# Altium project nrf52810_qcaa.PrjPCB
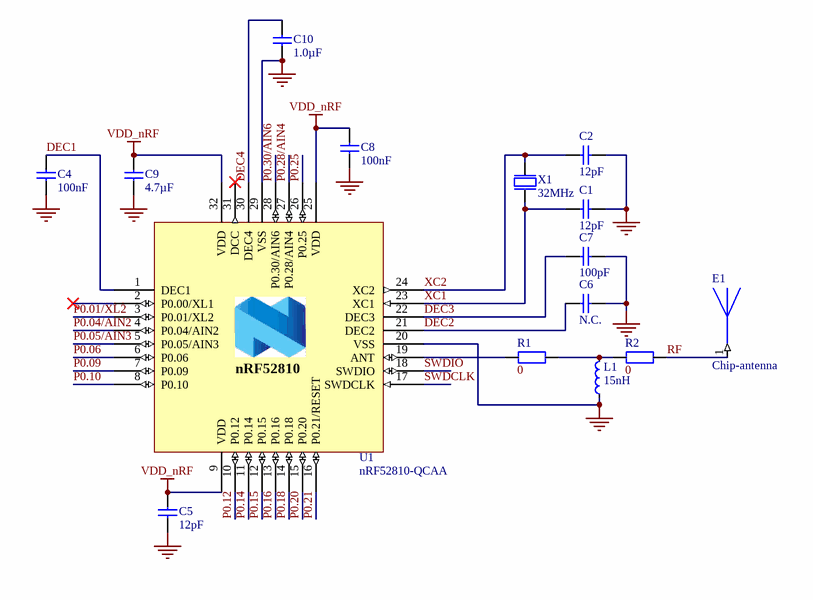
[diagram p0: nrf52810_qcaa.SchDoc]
1 sheet, 15 parts. Net scope: global (net labels, ports and power ports of the same name join across sheets).
Board file: nrf52810_qcaa.PcbDoc

## Sheet nrf52810_qcaa.SchDoc: nRF52810-QCAA Reference Layout
size A4; Revision: 1.0; SheetNumber: 1; SheetTotal: 1; DrawnBy: RUBR; DocumentSize: A4; PCAName: nRF52810-QCAA Reference Layout

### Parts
C1  12pF  [CAPC1005X04L]
C2  12pF  [CAPC1005X04L]
C4  100nF  [CAPC1005X04L]
C5  12pF  [CAPC1005X04L]
C6  N.C.  [CAPC1005X04L]
C7  100pF  [CAPC1005X04L]
C8  100nF  [CAPC1005X04L]
C9  4.7µF  [CAPC1608X06L]
C10  1.0µF  [CAPC1608X06L]
E1  Chip-antenna  [C03-chip-antenna]
L1  15nH  [INDC1005X04L]
R1  0  [R-0402-1005X40]
R2  0  [R-0402-1005X40]
U1  nRF52810-QCAA  [Nordic_QFN50P500X500X90-33N]
X1  32MHz  [BT-XTAL_2016]

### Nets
GND: C1.2 C2.2 C4.2 C5.2 C6.1 C7.2 C8.2 C9.2 C10.1 L1.1 U1.20(VSS) U1.29(VSS) U1.33 X1.2(GND) X1.4(GND)
VDD_nRF: C5.1 C8.1 C9.1 U1.9(VDD) U1.25(VDD) U1.32(VDD)
DEC1: C4.1 U1.1(DEC1)
DEC2: C6.2 U1.21(DEC2)
DEC3: C7.1 U1.22(DEC3)
DEC4: C10.2 U1.30(DEC4)
P0.01/XL2: U1.3(P0.01/XL2)
P0.04/AIN2: U1.4(P0.04/AIN2)
P0.05/AIN3: U1.5(P0.05/AIN3)
P0.06: U1.6(P0.06)
P0.09: U1.7(P0.09)
P0.10: U1.8(P0.10)
P0.12: U1.10(P0.12)
P0.14: U1.11(P0.14)
P0.15: U1.12(P0.15)
P0.16: U1.13(P0.16)
P0.18: U1.14(P0.18)
P0.20: U1.15(P0.20)
P0.21: U1.16(P0.21/RESET)
P0.25: U1.26(P0.25)
P0.28/AIN4: U1.27(P0.28/AIN4)
P0.30/AIN6: U1.28(P0.30/AIN6)
RF: E1.1(FEED) R2.2
SWDCLK: U1.17(SWDCLK)
SWDIO: U1.18(SWDIO)
XC1: C1.1 U1.23(XC1) X1.1(inp)
XC2: C2.1 U1.24(XC2) X1.3(out)
NetL1_2: L1.2 R1.2 R2.1
NetR1_1: R1.1 U1.19(ANT)

Not connected (* = marked no-connect by the designer): U1 2(P0.00/XL1)* 31(DCC)*

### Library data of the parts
C1 C2 = C0402-12p: Capacitor, NP0, ±2%; Note: 50V
C4 C8 = C0402-100n: Capacitor, X7R, ±10%; Note: 16V
C5 = CAP_0402: Capacitor, NP0, ±2%; Part Number: C0402-12p; Note: 50V
C6 = C0402-N.C.: Not mounted; Assembly: Not mounted
C7 = C0402-100p: Capacitor, NP0, ±5%; Note: 50V
C9 = C0603-4µ7: Capacitor, X5R, ±10%; Note: 6.3V
C10 = C0603-1µ0: Capacitor, X7R, ±10%; Note: 16V
E1 = Chip-antenna: antenna; MF: Linx; MP: ANT-868-CHP-T
L1 = IND_0402: High frequency chip inductor ±10%; Part Number: L0402-15n
R1 R2 = R-0402: 0402
U1 = nRF52810-QCAA: Multi-protocol Bluetooth Low Energy, ANT and 2.4GHz proprietary system-on-chip; Manufacturer: Nordic Semiconductor; Note: nRF52810 - QFN32 5x5 0.5mm pitch
X1 = XTAL_SMD2016_32MHz_8pF_General: XTAL SMD 2016, 32MHz, Cl=8pF, Total Tol: ±40ppm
